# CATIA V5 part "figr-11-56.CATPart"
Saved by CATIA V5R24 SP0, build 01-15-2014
Part number: Part1
Bounding box of the stored display mesh (mm): x -50 to 50, y -100 to 150, z -20 to 9.95
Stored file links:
  D:\KAVITA\CATIA V5-6R2014 Project_ Kavita\CATIA V5-6R2014_partfiles\Partfiles\c11_catia_v5-6r2014_prt\figr-11-56.CATPart
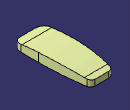
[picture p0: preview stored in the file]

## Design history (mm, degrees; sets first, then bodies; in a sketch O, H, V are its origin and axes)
Set1
  Extrude1: Element1 Sketch2, Lim1 50, Lim2 50, Direction yz-plane
  Sketch1 on xy-plane, origin (0, 0, 0), H (1, 0, 0), V (0, 1, 0)
    arc A1 centre (25, -75) radius 25 from (25, -100) to (50, -75) ccw
    line L1 (50, -75) -> (50, -15)
    point P4 (50, -15)
    arc A2 centre (-950, -15) radius 1000 from (50, -15) to (38.3367, 137.2843) ccw
    line L2 (23.5117, 150) -> (-23.5117, 150)
    line L3 (25, -100) -> (-25, -100)
    arc A3 centre (-25, -75) radius 25 from (-25, -100) to (-50, -75) cw
    line L4 (-50, -75) -> (-50, -15)
    point P9 (-50, -15)
    arc A4 centre (950, -15) radius 1000 from (-50, -15) to (-38.3367, 137.2843) cw
    reference projected line E1 (-50, -100) -> (50, -100) from edge of Extrude1
    axis line L5 (0, 170.4214) -> (0, -120.6595)
    point P11 (0, 170.4214)
    reference projected line E2 (50, -70) -> (50, 129.9971) from edge of Extrude1
    reference projected line E3 (-50, 129.9971) -> (-50, -70) from edge of Extrude1
    reference projected line E4 (-50, -100) -> (50, -100) from edge of Extrude1
    reference projected line E5 (50, 150) -> (-50, 150) from edge of Extrude1
    arc A5 centre (-23.5117, 135) radius 15 from (-38.3367, 137.2843) to (-23.5117, 150) cw
    arc A6 centre (23.5117, 135) radius 15 from (38.3367, 137.2843) to (23.5117, 150) ccw
    distance E4 P4 = 85
    radius A2 = 1000
    radius A5 = 15
    radius A6 = 15
    radius A1 = 25
    radius A3 = 25
    radius A4 = 1000
    tangency: L1 A1, A2 L1, L3 A1, A3 L3, A4 L4, L5 A3, A5 L2, A5 A4, A6 A2, A6 L2, A3 L4
    horizontal: L2 H
    coincidence: L3 E1, P11 V, L1 E2, L4 E3, L2 E5
    symmetry: P4 P9 L5
  Extrude2: Element1 Sketch1, Lim1 50, Lim2 20, Direction xy-plane
  Intersect1: ToIntersect1 Extrude1, ToIntersect2 Extrude2
  Split1: ToCut Extrude2, Cutting Extrude1
  Trim1: Trimmed (Extrude1; Split1)
Body1 (main body)
  Sketch2 on yz-plane, origin (0, 0, 0), H (0, 1, 0), V (0, 0, 1)
    point P1 (-100, 0)
    line L1 (-100, 0) -> (-70, 3.8724)
    point P2 (-70, 3.8724)
    arc A1 centre (26.0141, -739.9564) radius 750 from (-70, 3.8724) to (129.9971, 2.8003) cw
    point P4 (129.9971, 2.8003)
    line L2 (129.9971, 2.8003) -> (150, 0)
    point P5 (150, 0)
    distance P1 P5 = 250
    distance P1 O = 100
    radius A1 = 750
    distance P2 P4 = 200
    distance P2 V = 70
    coincidence: P1 H, P5 H
    tangency: A1 L1, L2 A1
  ThickSurface1: BotOffset 0, Surface Extrude1, TopOffset 5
